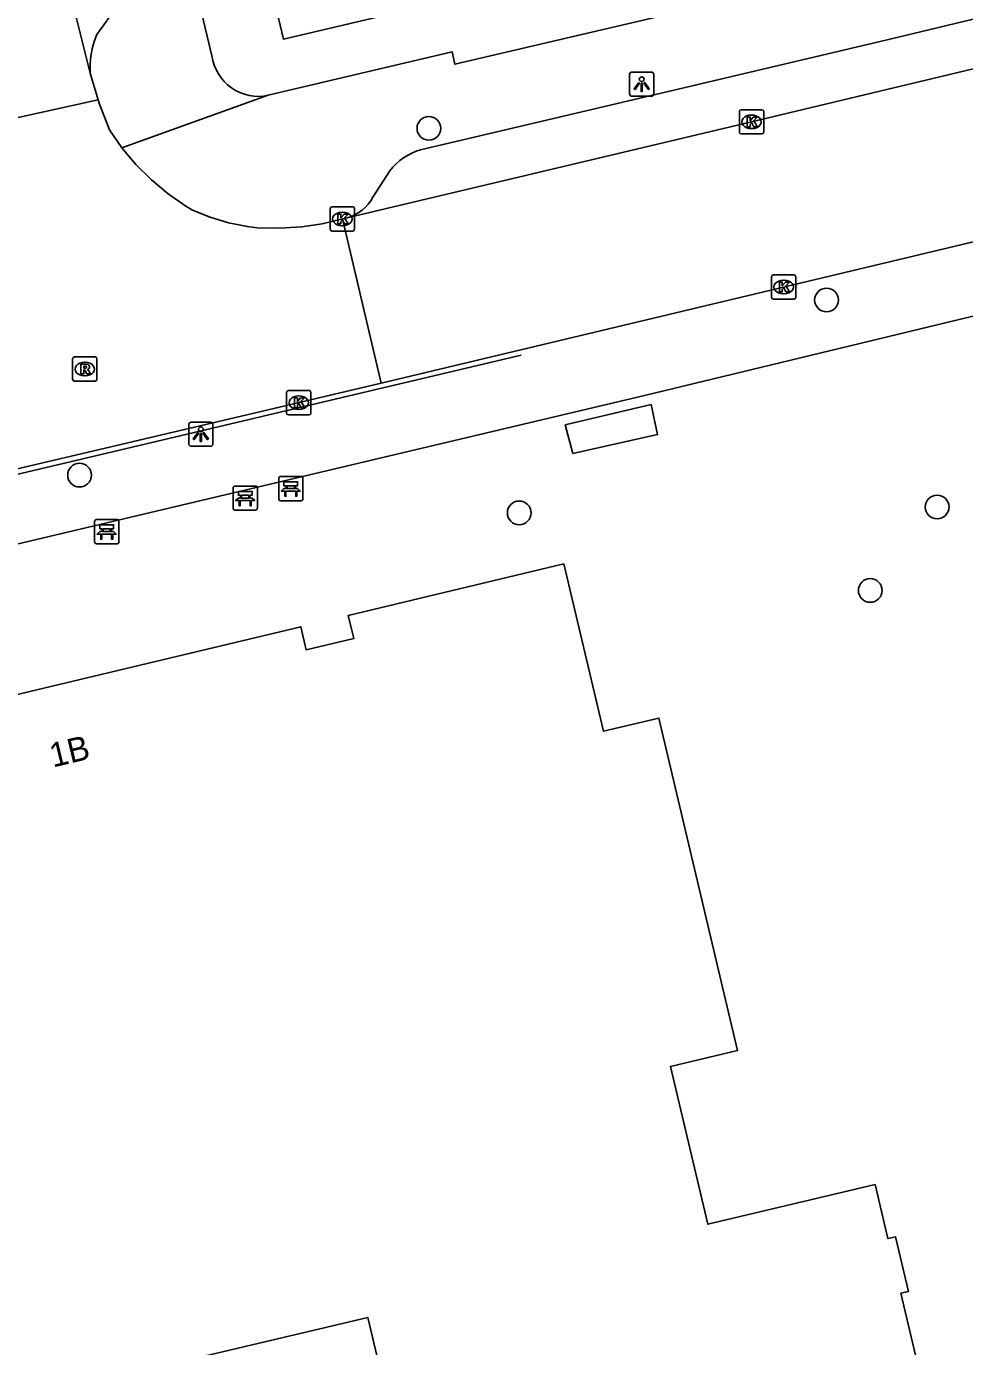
# Model space of a CAD drawing. Extents: x 158038 to 159242, y 380133 to 381214.
# Drawn here: x 158624 to 158662.7, y 380670.9 to 380725.4 of the extents above; entities that cross this region are included whole.
import ezdxf

# ---------------------------------------------------------------- set-up
doc = ezdxf.new("R2010")
doc.units = 0
for name, color, linetype in [('IMGEO_Bank', 7, 'Continuous'), ('IMGEO_Boom', 7, 'Continuous'), ('IMGEO_Hek', 7, 'Continuous'), ('IMGEO_Kolk', 7, 'Continuous'), ('IMGEO_Lichtpunt', 7, 'Continuous'), ('IMGEO_Muur', 7, 'Continuous'), ('IMGEO_Pand', 7, 'Continuous'), ('IMGEO_Pand_nummerreeks', 7, 'Continuous'), ('IMGEO_Rijbaan_lokaal_gesloten', 7, 'Continuous'), ('IMGEO_Rioolput', 7, 'Continuous'), ('IMGEO_Voetpad_gesloten', 7, 'Continuous'), ('IMGEO_Voetpad_open', 7, 'Continuous')]:
    doc.layers.add(name, color=color, linetype=linetype)

msp = doc.modelspace()

# ---------------------------------------------------------------- linework, layer by layer
at = {"layer": 'IMGEO_Bank'}
for p, q in [((158634.373, 380705.868), (158634.373, 380706.709)), ((158634.373, 380706.709), (158634.373, 380705.868)), ((158634.448, 380706.793), (158635.289, 380706.793)), ((158635.289, 380706.793), (158634.448, 380706.793)), ((158635.373, 380706.718), (158635.373, 380705.877)), ((158635.373, 380705.877), (158635.373, 380706.718)), ((158632.493, 380705.473), (158632.493, 380706.314)), ((158632.493, 380706.314), (158632.493, 380705.473)), ((158632.568, 380706.398), (158633.409, 380706.398)), ((158633.409, 380706.398), (158632.568, 380706.398)), ((158632.802, 380705.904), (158632.802, 380706.01)), ((158632.846, 380706.01), (158632.846, 380705.904)), ((158633.134, 380706.016), (158632.852, 380706.016)), ((158633.14, 380705.904), (158633.14, 380706.01)), ((158633.184, 380706.01), (158633.184, 380705.904)), ((158633.493, 380706.323), (158633.493, 380705.482)), ((158633.493, 380705.482), (158633.493, 380706.323)), ((158635.07, 380706.191), (158634.677, 380706.191)), ((158634.682, 380706.299), (158634.682, 380706.405)), ((158634.726, 380706.405), (158634.726, 380706.299)), ((158635.014, 380706.411), (158634.732, 380706.411)), ((158634.732, 380706.293), (158635.014, 380706.293)), ((158635.02, 380706.299), (158635.02, 380706.405)), ((158635.064, 380706.405), (158635.064, 380706.299)), ((158633.19, 380705.796), (158632.797, 380705.796)), ((158632.852, 380705.898), (158633.134, 380705.898)), ((158635.298, 380705.793), (158634.457, 380705.793)), ((158634.457, 380705.793), (158635.298, 380705.793)), ((158626.783, 380704.094), (158626.783, 380704.935)), ((158626.783, 380704.935), (158626.783, 380704.094)), ((158626.858, 380705.019), (158627.699, 380705.019)), ((158627.699, 380705.019), (158626.858, 380705.019)), ((158627.783, 380704.944), (158627.783, 380704.103)), ((158627.783, 380704.103), (158627.783, 380704.944)), ((158633.418, 380705.398), (158632.577, 380705.398)), ((158632.577, 380705.398), (158633.418, 380705.398)), ((158627.48, 380704.417), (158627.087, 380704.417)), ((158627.092, 380704.525), (158627.092, 380704.631)), ((158627.136, 380704.631), (158627.136, 380704.525)), ((158627.424, 380704.637), (158627.142, 380704.637)), ((158627.142, 380704.519), (158627.424, 380704.519)), ((158627.43, 380704.525), (158627.43, 380704.631)), ((158627.474, 380704.631), (158627.474, 380704.525)), ((158627.708, 380704.019), (158626.867, 380704.019)), ((158626.867, 380704.019), (158627.708, 380704.019))]:
    msp.add_line(p, q, dxfattribs=at)
for points in [[(158634.676, 380706.411), (158634.59, 380706.411), (158634.59, 380706.572), (158635.153, 380706.572), (158635.153, 380706.411), (158635.07, 380706.411)], [(158632.796, 380706.016), (158632.71, 380706.016), (158632.71, 380706.177), (158633.273, 380706.177), (158633.273, 380706.016), (158633.19, 380706.016)], [(158634.62, 380706.191), (158634.478, 380706.191), (158634.59, 380706.293), (158634.676, 380706.293)], [(158634.67, 380706.184), (158634.67, 380705.977), (158634.627, 380705.977), (158634.627, 380706.184)], [(158635.07, 380706.293), (158635.153, 380706.293), (158635.265, 380706.191), (158635.126, 380706.191)], [(158635.12, 380706.184), (158635.12, 380705.977), (158635.076, 380705.977), (158635.076, 380706.184)], [(158632.74, 380705.796), (158632.598, 380705.796), (158632.71, 380705.898), (158632.796, 380705.898)], [(158632.79, 380705.789), (158632.79, 380705.582), (158632.747, 380705.582), (158632.747, 380705.789)], [(158633.19, 380705.898), (158633.273, 380705.898), (158633.385, 380705.796), (158633.246, 380705.796)], [(158633.24, 380705.789), (158633.24, 380705.582), (158633.196, 380705.582), (158633.196, 380705.789)], [(158627.03, 380704.417), (158626.888, 380704.417), (158627, 380704.519), (158627.086, 380704.519)], [(158627.086, 380704.637), (158627, 380704.637), (158627, 380704.798), (158627.563, 380704.798), (158627.563, 380704.637), (158627.48, 380704.637)], [(158627.08, 380704.41), (158627.08, 380704.203), (158627.037, 380704.203), (158627.037, 380704.41)], [(158627.48, 380704.519), (158627.563, 380704.519), (158627.675, 380704.417), (158627.536, 380704.417)], [(158627.53, 380704.41), (158627.53, 380704.203), (158627.486, 380704.203), (158627.486, 380704.41)]]:
    msp.add_lwpolyline(points, dxfattribs=at)
for centre, radius, start, end in [((158634.451, 380706.715), 0.0779, 92.4484, 184.2845), ((158634.451, 380706.715), 0.0779, 92.4484, 184.2845), ((158635.295, 380706.715), 0.0779, 2.4484, 94.2845), ((158635.295, 380706.715), 0.0779, 2.4484, 94.2845), ((158632.571, 380706.32), 0.0779, 92.4484, 184.2845), ((158632.571, 380706.32), 0.0779, 92.4484, 184.2845), ((158632.795, 380706.009), 0.00671, 2.8957, 87.1043), ((158632.852, 380706.009), 0.00671, 92.8957, 177.1043), ((158633.134, 380706.009), 0.00671, 2.8957, 87.1043), ((158633.191, 380706.009), 0.00671, 92.8957, 177.1043), ((158633.415, 380706.32), 0.0779, 2.4484, 94.2845), ((158633.415, 380706.32), 0.0779, 2.4484, 94.2845), ((158634.62, 380706.184), 0.00671, 2.8957, 87.1043), ((158634.677, 380706.184), 0.00671, 92.8957, 177.1043), ((158634.675, 380706.404), 0.00671, 2.8957, 87.1043), ((158634.675, 380706.3), 0.00671, 272.8957, 357.1043), ((158634.732, 380706.404), 0.00671, 92.8957, 177.1043), ((158634.732, 380706.3), 0.00671, 182.8957, 267.1043), ((158635.014, 380706.404), 0.00671, 2.8957, 87.1043), ((158635.014, 380706.3), 0.00671, 272.8957, 357.1043), ((158635.071, 380706.404), 0.00671, 92.8957, 177.1043), ((158635.071, 380706.3), 0.00671, 182.8957, 267.1043), ((158635.069, 380706.184), 0.00671, 2.8957, 87.1043), ((158635.126, 380706.184), 0.00671, 92.8957, 177.1043), ((158632.571, 380705.476), 0.0779, 182.4484, 274.2845), ((158632.571, 380705.476), 0.0779, 182.4484, 274.2845), ((158632.74, 380705.789), 0.00671, 2.8957, 87.1043), ((158632.797, 380705.789), 0.00671, 92.8957, 177.1043), ((158632.795, 380705.905), 0.00671, 272.8957, 357.1043), ((158632.852, 380705.905), 0.00671, 182.8957, 267.1043), ((158633.134, 380705.905), 0.00671, 272.8957, 357.1043), ((158633.191, 380705.905), 0.00671, 182.8957, 267.1043), ((158633.189, 380705.789), 0.00671, 2.8957, 87.1043), ((158633.246, 380705.789), 0.00671, 92.8957, 177.1043), ((158633.415, 380705.476), 0.0779, 272.4484, 4.2845), ((158633.415, 380705.476), 0.0779, 272.4484, 4.2845), ((158634.451, 380705.871), 0.0779, 182.4484, 274.2845), ((158634.451, 380705.871), 0.0779, 182.4484, 274.2845), ((158635.295, 380705.871), 0.0779, 272.4484, 4.2845), ((158635.295, 380705.871), 0.0779, 272.4484, 4.2845), ((158626.861, 380704.941), 0.0779, 92.4484, 184.2845), ((158626.861, 380704.941), 0.0779, 92.4484, 184.2845), ((158627.705, 380704.941), 0.0779, 2.4484, 94.2845), ((158627.705, 380704.941), 0.0779, 2.4484, 94.2845), ((158627.03, 380704.41), 0.00671, 2.8957, 87.1043), ((158627.087, 380704.41), 0.00671, 92.8957, 177.1043), ((158627.085, 380704.63), 0.00671, 2.8957, 87.1043), ((158627.085, 380704.526), 0.00671, 272.8957, 357.1043), ((158627.142, 380704.63), 0.00671, 92.8957, 177.1043), ((158627.142, 380704.526), 0.00671, 182.8957, 267.1043), ((158627.424, 380704.63), 0.00671, 2.8957, 87.1043), ((158627.424, 380704.526), 0.00671, 272.8957, 357.1043), ((158627.481, 380704.63), 0.00671, 92.8957, 177.1043), ((158627.481, 380704.526), 0.00671, 182.8957, 267.1043), ((158627.479, 380704.41), 0.00671, 2.8957, 87.1043), ((158627.536, 380704.41), 0.00671, 92.8957, 177.1043), ((158626.861, 380704.097), 0.0779, 182.4484, 274.2845), ((158626.861, 380704.097), 0.0779, 182.4484, 274.2845), ((158627.705, 380704.097), 0.0779, 272.4484, 4.2845), ((158627.705, 380704.097), 0.0779, 272.4484, 4.2845)]:
    msp.add_arc(centre, radius, start, end, dxfattribs=at)
at = {"layer": 'IMGEO_Boom'}
for centre in [(158640.567, 380721.156), (158656.963, 380714.072), (158626.161, 380706.848), (158661.525, 380705.534), (158644.293, 380705.29), (158658.767, 380702.092)]:
    msp.add_circle(centre, 0.489, dxfattribs=at)
at = {"layer": 'IMGEO_Hek'}
msp.add_lwpolyline([(158616.35, 380705.173), (158644.367, 380711.795)], dxfattribs=at)
at = {"layer": 'IMGEO_Kolk'}
for p, q in [((158653.371, 380720.996), (158653.371, 380721.848)), ((158653.446, 380721.922), (158654.298, 380721.922)), ((158654.372, 380721.848), (158654.372, 380720.996)), ((158653.859, 380721.702), (158653.884, 380721.702)), ((158654.298, 380720.922), (158653.446, 380720.922)), ((158653.882, 380721.142), (158653.857, 380721.142)), ((158636.497, 380716.992), (158636.497, 380717.844)), ((158636.572, 380717.918), (158637.424, 380717.918)), ((158636.985, 380717.698), (158637.01, 380717.698)), ((158637.498, 380717.844), (158637.498, 380716.992)), ((158637.424, 380716.918), (158636.572, 380716.918)), ((158637.008, 380717.138), (158636.983, 380717.138)), ((158654.697, 380714.183), (158654.697, 380715.035)), ((158654.772, 380715.109), (158655.624, 380715.109)), ((158655.185, 380714.889), (158655.21, 380714.889)), ((158655.698, 380715.035), (158655.698, 380714.183)), ((158655.208, 380714.329), (158655.183, 380714.329)), ((158655.624, 380714.109), (158654.772, 380714.109)), ((158634.701, 380709.408), (158634.701, 380710.26)), ((158634.776, 380710.334), (158635.628, 380710.334)), ((158635.189, 380710.114), (158635.214, 380710.114)), ((158635.702, 380710.26), (158635.702, 380709.408)), ((158635.628, 380709.334), (158634.776, 380709.334)), ((158635.212, 380709.554), (158635.187, 380709.554))]:
    msp.add_line(p, q, dxfattribs=at)
for points in [[(158653.371, 380720.996), (158653.371, 380721.848)], [(158653.446, 380721.922), (158654.298, 380721.922)], [(158654.372, 380721.848), (158654.372, 380720.996)], [(158653.692, 380721.622), (158653.815, 380721.622), (158653.815, 380721.471), (158653.945, 380721.622), (158654.109, 380721.622), (158653.963, 380721.471), (158654.116, 380721.222), (158653.964, 380721.222), (158653.879, 380721.386), (158653.815, 380721.319), (158653.815, 380721.222), (158653.692, 380721.222), (158653.692, 380721.622)], [(158654.298, 380720.922), (158653.446, 380720.922)], [(158636.497, 380716.992), (158636.497, 380717.844)], [(158636.572, 380717.918), (158637.424, 380717.918)], [(158636.818, 380717.618), (158636.941, 380717.618), (158636.941, 380717.467), (158637.071, 380717.618), (158637.235, 380717.618), (158637.089, 380717.467), (158637.242, 380717.218), (158637.09, 380717.218), (158637.005, 380717.382), (158636.941, 380717.315), (158636.941, 380717.218), (158636.818, 380717.218), (158636.818, 380717.618)], [(158637.498, 380717.844), (158637.498, 380716.992)], [(158637.424, 380716.918), (158636.572, 380716.918)], [(158654.697, 380714.183), (158654.697, 380715.035)], [(158654.772, 380715.109), (158655.624, 380715.109)], [(158655.018, 380714.809), (158655.141, 380714.809), (158655.141, 380714.658), (158655.271, 380714.809), (158655.435, 380714.809), (158655.289, 380714.658), (158655.442, 380714.409), (158655.29, 380714.409), (158655.205, 380714.573), (158655.141, 380714.506), (158655.141, 380714.409), (158655.018, 380714.409), (158655.018, 380714.809)], [(158655.698, 380715.035), (158655.698, 380714.183)], [(158655.624, 380714.109), (158654.772, 380714.109)], [(158634.701, 380709.408), (158634.701, 380710.26)], [(158634.776, 380710.334), (158635.628, 380710.334)], [(158635.022, 380710.034), (158635.145, 380710.034), (158635.145, 380709.883), (158635.275, 380710.034), (158635.439, 380710.034), (158635.293, 380709.883), (158635.446, 380709.634), (158635.294, 380709.634), (158635.209, 380709.798), (158635.145, 380709.731), (158635.145, 380709.634), (158635.022, 380709.634), (158635.022, 380710.034)], [(158635.702, 380710.26), (158635.702, 380709.408)], [(158635.628, 380709.334), (158634.776, 380709.334)]]:
    msp.add_lwpolyline(points, dxfattribs=at)
for centre, start, end in [((158653.448, 380721.846), 91.552, 178.448), ((158653.448, 380721.846), 91.552, 178.448), ((158654.296, 380721.846), 1.552, 88.448), ((158654.296, 380721.846), 1.552, 88.448), ((158653.448, 380720.998), 181.552, 268.448), ((158653.448, 380720.998), 181.552, 268.448), ((158654.296, 380720.998), 271.552, 358.448), ((158654.296, 380720.998), 271.552, 358.448), ((158636.574, 380717.842), 91.552, 178.448), ((158636.574, 380717.842), 91.552, 178.448), ((158637.422, 380717.842), 1.552, 88.448), ((158637.422, 380717.842), 1.552, 88.448), ((158636.574, 380716.994), 181.552, 268.448), ((158636.574, 380716.994), 181.552, 268.448), ((158637.422, 380716.994), 271.552, 358.448), ((158637.422, 380716.994), 271.552, 358.448), ((158654.774, 380715.033), 91.552, 178.448), ((158654.774, 380715.033), 91.552, 178.448), ((158655.622, 380715.033), 1.552, 88.448), ((158655.622, 380715.033), 1.552, 88.448), ((158654.774, 380714.185), 181.552, 268.448), ((158654.774, 380714.185), 181.552, 268.448), ((158655.622, 380714.185), 271.552, 358.448), ((158655.622, 380714.185), 271.552, 358.448), ((158634.778, 380710.258), 91.552, 178.448), ((158634.778, 380710.258), 91.552, 178.448), ((158635.626, 380710.258), 1.552, 88.448), ((158635.626, 380710.258), 1.552, 88.448), ((158634.778, 380709.41), 181.552, 268.448), ((158634.778, 380709.41), 181.552, 268.448), ((158635.626, 380709.41), 271.552, 358.448), ((158635.626, 380709.41), 271.552, 358.448)]:
    msp.add_arc(centre, 0.0765, start, end, dxfattribs=at)
for centre, major_axis, ratio, start_param, end_param in [((158653.858, 380721.422), (-0.387, 0.002), 0.722429, 4.712389, 7.853982), ((158653.883, 380721.422), (-0.39, 0.002), 0.717154, 1.570796, 4.712389), ((158636.984, 380717.418), (-0.387, 0.002), 0.722429, 4.712389, 7.853982), ((158637.009, 380717.418), (-0.39, 0.002), 0.717154, 1.570796, 4.712389), ((158655.184, 380714.609), (-0.387, 0.002), 0.722429, 4.712389, 7.853982), ((158655.209, 380714.609), (-0.39, 0.002), 0.717154, 1.570796, 4.712389), ((158635.188, 380709.834), (-0.387, 0.002), 0.722429, 4.712389, 7.853982), ((158635.213, 380709.834), (-0.39, 0.002), 0.717154, 1.570796, 4.712389)]:
    msp.add_ellipse(centre, major_axis=major_axis, ratio=ratio, start_param=start_param, end_param=end_param, dxfattribs=at)
at = {"layer": 'IMGEO_Lichtpunt'}
for p, q in [((158649.746, 380723.477), (158648.938, 380723.477)), ((158649.746, 380723.477), (158648.938, 380723.477)), ((158648.844, 380723.382), (158648.844, 380722.575)), ((158648.844, 380723.382), (158648.844, 380722.575)), ((158649.84, 380722.575), (158649.84, 380723.382)), ((158649.84, 380722.575), (158649.84, 380723.382)), ((158648.938, 380722.481), (158649.746, 380722.481)), ((158648.938, 380722.481), (158649.746, 380722.481)), ((158630.666, 380708.938), (158630.666, 380708.131)), ((158630.666, 380708.938), (158630.666, 380708.131)), ((158631.568, 380709.033), (158630.76, 380709.033)), ((158631.568, 380709.033), (158630.76, 380709.033)), ((158631.662, 380708.131), (158631.662, 380708.938)), ((158631.662, 380708.131), (158631.662, 380708.938)), ((158630.76, 380708.037), (158631.568, 380708.037)), ((158630.76, 380708.037), (158631.568, 380708.037))]:
    msp.add_line(p, q, dxfattribs=at)
for points in [[(158649.218, 380723.046), (158649.257, 380723.018), (158649.069, 380722.756), (158649.031, 380722.783), (158649.218, 380723.046)], [(158649.32, 380722.998), (158649.367, 380722.998), (158649.367, 380722.676), (158649.32, 380722.676), (158649.32, 380722.998)], [(158649.43, 380723.018), (158649.468, 380723.045), (158649.655, 380722.783), (158649.616, 380722.755), (158649.43, 380723.018)], [(158631.04, 380708.602), (158631.079, 380708.574), (158630.891, 380708.312), (158630.853, 380708.339), (158631.04, 380708.602)], [(158631.142, 380708.554), (158631.189, 380708.554), (158631.189, 380708.232), (158631.142, 380708.232), (158631.142, 380708.554)], [(158631.252, 380708.574), (158631.29, 380708.601), (158631.477, 380708.339), (158631.438, 380708.311), (158631.252, 380708.574)]]:
    msp.add_lwpolyline(points, dxfattribs=at)
for centre in [(158649.343, 380723.18), (158631.165, 380708.736)]:
    msp.add_circle(centre, 0.0994, dxfattribs=at)
for centre, start, end in [((158648.938, 380723.382), 90, 180), ((158648.938, 380723.382), 90, 180), ((158649.746, 380723.382), 0, 90), ((158649.746, 380723.382), 0, 90), ((158648.938, 380722.575), 180, 270), ((158648.938, 380722.575), 180, 270), ((158649.746, 380722.575), 270, 0), ((158649.746, 380722.575), 270, 360), ((158630.76, 380708.938), 90, 180), ((158630.76, 380708.938), 90, 180), ((158631.568, 380708.938), 0, 90), ((158631.568, 380708.938), 0, 90), ((158630.76, 380708.131), 180, 270), ((158630.76, 380708.131), 180, 270), ((158631.568, 380708.131), 270, 0), ((158631.568, 380708.131), 270, 360)]:
    msp.add_arc(centre, 0.0946, start, end, dxfattribs=at)
at = {"layer": 'IMGEO_Muur'}
msp.add_lwpolyline([(158641.632, 380723.796), (158651.055, 380726.009)], dxfattribs=at)
at = {"layer": 'IMGEO_Pand'}
for points in [[(158641.865, 380732.984), (158641.901, 380732.83), (158644.618, 380733.469), (158645.528, 380729.592), (158644.208, 380729.282), (158644.637, 380727.467), (158643.174, 380727.121), (158643.232, 380726.876), (158634.571, 380724.828), (158633.134, 380730.912)], [(158661.915, 380665.137), (158660.028, 380673.097), (158660.349, 380673.173), (158659.814, 380675.43), (158659.493, 380675.354), (158658.965, 380677.582), (158652.066, 380675.947), (158650.523, 380682.456), (158653.296, 380683.113), (158650.049, 380696.822), (158647.764, 380696.28), (158646.129, 380703.183), (158637.24, 380701.059), (158637.468, 380700.107), (158635.513, 380699.64), (158635.285, 380700.593), (158614.708, 380695.685)], [(158625.302, 380669.083), (158638.047, 380672.1), (158640.878, 380660.15)]]:
    msp.add_lwpolyline(points, dxfattribs=at)
at = {"layer": 'IMGEO_Rijbaan_lokaal_gesloten'}
for points in [[(158626.597, 380723.434), (158625.847, 380726.467), (158625.599, 380727.516)], [(158677.444, 380727.07), (158653.812, 380721.407), (158637.203, 380717.466)], [(158626.931, 380722.326), (158626.597, 380723.434)], [(158620.191, 380720.852), (158626.931, 380722.326)], [(158626.931, 380722.326), (158626.982, 380722.155), (158627.4, 380721.092), (158627.912, 380720.355)], [(158627.912, 380720.355), (158628.487, 380719.666), (158629.122, 380719.031), (158629.811, 380718.456), (158630.549, 380717.944), (158630.818, 380717.781), (158631.552, 380717.488), (158632.309, 380717.262), (158633.083, 380717.105), (158633.486, 380717.051), (158634.406, 380717.03), (158635.324, 380717.091), (158636.169, 380717.221), (158637.007, 380717.42)], [(158678.337, 380720.133), (158638.594, 380710.645)], [(158637.203, 380717.466), (158637.007, 380717.42)], [(158637.007, 380717.42), (158638.594, 380710.645)], [(158638.594, 380710.645), (158635.165, 380709.826), (158615.004, 380705.091), (158610.098, 380703.953)]]:
    msp.add_lwpolyline(points, dxfattribs=at)
at = {"layer": 'IMGEO_Rioolput'}
for p, q in [((158625.878, 380710.798), (158625.878, 380711.65)), ((158625.953, 380711.724), (158626.805, 380711.724)), ((158626.366, 380711.504), (158626.391, 380711.504)), ((158626.879, 380711.65), (158626.879, 380710.798)), ((158626.389, 380710.944), (158626.364, 380710.944)), ((158626.805, 380710.724), (158625.953, 380710.724))]:
    msp.add_line(p, q, dxfattribs=at)
for points in [[(158625.878, 380710.798), (158625.878, 380711.65)], [(158625.953, 380711.724), (158626.805, 380711.724)], [(158626.879, 380711.65), (158626.879, 380710.798)], [(158626.467, 380711.422), (158626.215, 380711.424), (158626.215, 380711.024)], [(158626.215, 380711.024), (158626.339, 380711.024), (158626.339, 380711.186), (158626.35, 380711.186)], [(158626.393, 380711.343), (158626.339, 380711.343), (158626.339, 380711.262)], [(158626.339, 380711.262), (158626.391, 380711.262)], [(158626.397, 380711.157), (158626.468, 380711.024), (158626.608, 380711.024), (158626.543, 380711.15)], [(158626.805, 380710.724), (158625.953, 380710.724)]]:
    msp.add_lwpolyline(points, dxfattribs=at)
for centre, radius, start, end in [((158625.955, 380711.648), 0.0765, 91.552, 178.448), ((158625.955, 380711.648), 0.0765, 91.552, 178.448), ((158626.803, 380711.648), 0.0765, 1.552, 88.448), ((158626.803, 380711.648), 0.0765, 1.552, 88.448), ((158626.349, 380711.133), 0.0533, 26.0293, 88.6989), ((158626.375, 380711.451), 0.19, 274.7715, 282.9687), ((158626.399, 380711.247), 0.0964, 77.0061, 93.1865), ((158626.413, 380711.304), 0.0378, 276.6634, 79.6772), ((158626.466, 380711.312), 0.109, 350.3612, 89.416), ((158626.464, 380711.312), 0.112, 277.5842, 350.9817), ((158626.448, 380711.097), 0.108, 29.5134, 73.7905), ((158625.955, 380710.8), 0.0765, 181.552, 268.448), ((158625.955, 380710.8), 0.0765, 181.552, 268.448), ((158626.803, 380710.8), 0.0765, 271.552, 358.448), ((158626.803, 380710.8), 0.0765, 271.552, 358.448)]:
    msp.add_arc(centre, radius, start, end, dxfattribs=at)
for centre, major_axis, ratio, start_param, end_param in [((158626.365, 380711.224), (-0.387, 0.002), 0.722429, 4.712389, 7.853982), ((158626.39, 380711.224), (-0.39, 0.002), 0.717154, 1.570796, 4.712389)]:
    msp.add_ellipse(centre, major_axis=major_axis, ratio=ratio, start_param=start_param, end_param=end_param, dxfattribs=at)
at = {"layer": 'IMGEO_Voetpad_gesloten'}
msp.add_lwpolyline([(158646.496, 380707.737), (158649.999, 380708.524), (158649.736, 380709.756), (158646.191, 380708.926), (158646.496, 380707.737)], dxfattribs=at)
at = {"layer": 'IMGEO_Voetpad_open'}
for points in [[(158613.34, 380779.174), (158615.415, 380779.644), (158620.656, 380757.457), (158621.53, 380753.756), (158622.417, 380750), (158627.774, 380727.324), (158627.799, 380727.151), (158627.808, 380726.976), (158627.801, 380726.802), (158627.779, 380726.628), (158627.741, 380726.458), (158627.689, 380726.291), (158627.621, 380726.129), (158627.54, 380725.975), (158627.445, 380725.828), (158626.88, 380725.02), (158626.769, 380724.731), (158626.684, 380724.433), (158626.626, 380724.129), (158626.596, 380723.821), (158626.593, 380723.512), (158626.597, 380723.434)], [(158624.571, 380753.829), (158625.471, 380750), (158631.622, 380724.15)], [(158640.223, 380720.27), (158651.834, 380723.01), (158659.175, 380724.742), (158672.524, 380727.961), (158674.479, 380728.406)], [(158653.942, 380726.687), (158651.055, 380726.009), (158641.632, 380723.796), (158641.525, 380724.316), (158633.943, 380722.518)], [(158633.943, 380722.518), (158627.912, 380720.355)], [(158638.259, 380718.32), (158638.959, 380719.404)], [(158573.471, 380692.129), (158646.034, 380709.321), (158649.457, 380710.132), (158670.862, 380715.31), (158686.652, 380719.032)]]:
    msp.add_lwpolyline(points, dxfattribs=at)
for centre, radius, start, end in [((158633.538, 380724.409), 1.934, 187.6991, 282.0753), ((158640.915, 380717.904), 2.465, 106.3114, 142.5207), ((158636.729, 380719.132), 1.733, 285.8876, 332.0382)]:
    msp.add_arc(centre, radius, start, end, dxfattribs=at)

# ---------------------------------------------------------------- texts
at = {"layer": 'IMGEO_Pand_nummerreeks'}
msp.add_text('1B', height=1, rotation=13.4155, dxfattribs=at).set_placement((158625.064, 380694.783))

doc.saveas('drawing.dxf')
